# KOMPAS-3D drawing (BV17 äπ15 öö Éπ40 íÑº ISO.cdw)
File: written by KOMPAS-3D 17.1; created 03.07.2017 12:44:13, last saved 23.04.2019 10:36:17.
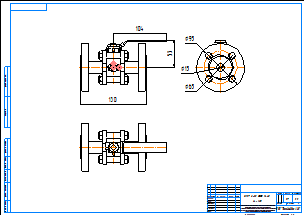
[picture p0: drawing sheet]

Sheet 1: A2, landscape

Title block, sheet 1: name: BV17 Ду15 ФФ Ру40 / без ISO; material: Внимание! Данный продукт является объектом авторского права ООО «Торговый Дом АДЛ». / Запрещается изменение, копирование, распространение / (в том числе путем копирования на другие сайты и ресурсы в Интернете) / или любое иное использование информации и объектов без предварительного / согласия правообладателя (ООО «Торговый Дом АДЛ»).; mass: 1,7; sheets: 1; organisation: ООО "Торговый дом АДЛ"; sheet format: A2; stored path: C:\Users\kka\KOMPAS_Work\!Trash\СС02 СС03 ФФ Смотровые стекла\СС01.cdw

Views: Спереди 1, Проекционный вид 2, Проекционный вид 3
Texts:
  Klimkovich
  ADL
Dimensions and other numbers on the sheet: 130; 104; 53; 65; 95; 15; 1:1; 1; 1,7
